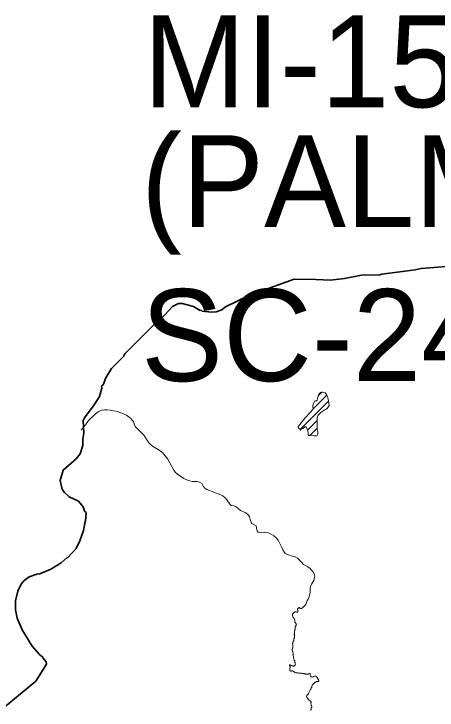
# Model space of a CAD drawing. Extents: x 553962 to 842807, y 8883888 to 9032388.
# Drawn here: x 608939 to 611239, y 8912510 to 8916296 of the extents above; entities that cross this region are included whole.
import ezdxf

# ---------------------------------------------------------------- set-up
doc = ezdxf.new("R2010")
doc.units = 0
doc.header["$LTSCALE"] = 200
doc.linetypes.add('LONG_DASH_SHORT_DASH', pattern=[9.9, 6, -1.2, 1.5, -1.2])
doc.layers.add('6', color=7, linetype='Continuous', lineweight=13)

msp = doc.modelspace()

# ---------------------------------------------------------------- linework, layer by layer
at = {"layer": '6'}
for p, q in [((610565.7, 8914148.7), (610640.2, 8914223.2)), ((610592.8, 8914218.2), (610613.2, 8914238.6)), ((610494, 8914034.6), (610649.5, 8914190.1)), ((610536, 8914034.2), (610587.2, 8914085.3)), ((610547.2, 8914002.9), (610587.8, 8914043.4))]:
    msp.add_line(p, q, dxfattribs=at)
at = {"layer": '6', "linetype": 'LONG_DASH_SHORT_DASH', "lineweight": 35}
for points in [[(609417, 8914259.9), (609414.5, 8914271.5), (609423.4, 8914278), (609438.5, 8914317.1), (609470.2, 8914368), (609534.8, 8914432.1), (609542.7, 8914447.8), (609726.2, 8914632.2), (609735.6, 8914633.7), (609801.8, 8914705.2), (609834.3, 8914720.4), (609853.1, 8914720.4), (609915.1, 8914705.6), (609951.4, 8914683.3), (609956.6, 8914684.2), (609962.2, 8914680.3), (610012.3, 8914673.4), (610039, 8914675), (610068.6, 8914686.7), (610088.4, 8914702.4), (610215.4, 8914764.3), (610462.8, 8914853.2), (610579.4, 8914851.9), (610659.1, 8914847.2), (610736.4, 8914857.9), (610829, 8914875.5), (610927.4, 8914877.4), (610939, 8914881.5), (611120.3, 8914903.8), (611152.1, 8914910.7), (611312, 8914924.8)], [(608880, 8912519.3), (609058.8, 8912666.4), (609116.5, 8912759.3), (609114.9, 8912772.6), (609096.2, 8912793.6), (609097.3, 8912795.6), (609078.6, 8912811.8), (609038.2, 8912857.6), (608983.3, 8912946.8), (608956.3, 8913009.1), (608946.9, 8913054.2), (608947.5, 8913104.1), (608959.7, 8913156.7), (608979, 8913193.9), (608994.6, 8913214.2), (609021.3, 8913233.8), (609062.8, 8913248.6), (609080.9, 8913251), (609139.7, 8913275.3), (609195.1, 8913310.8), (609228, 8913340.4), (609232.6, 8913340.3), (609276.6, 8913389.1), (609297.3, 8913429.6), (609318.1, 8913487), (609324.7, 8913524.3), (609323.1, 8913528.6), (609328.6, 8913536.8), (609332, 8913584.8), (609323.1, 8913590.8), (609315.6, 8913614.7), (609290.5, 8913645.2), (609240.2, 8913670.2), (609212.4, 8913694.1), (609201.8, 8913711), (609190.8, 8913757.9), (609207.3, 8913814.3), (609277.5, 8913876.2), (609298.7, 8913903.7), (609314.4, 8913949), (609314.4, 8913981.9), (609319.5, 8914018.2), (609315.7, 8914084.9), (609322.5, 8914099.7), (609375.2, 8914169.3), (609404.5, 8914214.5), (609417, 8914259.9)]]:
    msp.add_lwpolyline(points, dxfattribs=at)
at = {"layer": '6'}
for points in [[(610550.1, 8914128.2), (610522.6, 8914099.6), (610485.2, 8914054.4), (610484.5, 8914051.4), (610485.8, 8914043.6), (610490.9, 8914038.7), (610495.7, 8914032.3), (610498.2, 8914032.8), (610503.2, 8914038.6), (610511.3, 8914041.6), (610520, 8914049.9), (610522.6, 8914050.8), (610526.2, 8914050.7), (610528.6, 8914048), (610536.9, 8914032.6), (610538.2, 8914010.4), (610539.8, 8914005.3), (610541.1, 8914003.4), (610572.1, 8914000.6), (610584.6, 8914001.8), (610587.4, 8914003), (610591.6, 8914010.9), (610591.8, 8914024.6), (610588.8, 8914032.4), (610588, 8914036.4), (610586.7, 8914070.3), (610587.8, 8914099.9), (610590.6, 8914109.6), (610593.7, 8914113.9), (610608, 8914127.7), (610618.3, 8914134.6), (610625.4, 8914140.7), (610632.9, 8914144.4), (610642.7, 8914150.8), (610652.1, 8914166.7), (610649.1, 8914194), (610643.6, 8914215.7), (610640.1, 8914223.4), (610630.2, 8914235.9), (610618.4, 8914238.7)], [(610618.4, 8914238.7), (610613.1, 8914238.6), (610606, 8914236.5), (610596.3, 8914228.7), (610594.6, 8914224.8), (610586.9, 8914195.9), (610580.3, 8914189.7), (610574.4, 8914190.9), (610570.6, 8914185.2), (610568.3, 8914176.6), (610564.4, 8914166.3), (610563.7, 8914158.5), (610565.8, 8914148.4), (610564.8, 8914145.3), (610550.1, 8914128.2)], [(609417.9, 8914140.3), (609432.3, 8914143), (609446.8, 8914143.1), (609462, 8914141.3), (609500.2, 8914133.9), (609525, 8914125.2), (609551.2, 8914114.5), (609565.8, 8914103.2), (609574.5, 8914094.8), (609590.7, 8914075.3), (609593.5, 8914063.3), (609599.2, 8914050.6), (609647.6, 8914002.6), (609664.4, 8913973.8), (609675.8, 8913959.2), (609691.7, 8913944.3), (609718.8, 8913929.2), (609744.3, 8913912.2), (609754.5, 8913902), (609775.4, 8913874.4), (609799.6, 8913831.8), (609808, 8913815.2), (609816.3, 8913803.9), (609827.9, 8913793.1), (609863.5, 8913769.2), (609883, 8913759.4), (609908.5, 8913753.4), (609934, 8913752.3), (609948.3, 8913750), (609960, 8913741.4), (609967.7, 8913728.2), (609976.3, 8913717.3), (609987.7, 8913708.8), (610063.1, 8913680.4), (610075.6, 8913674.7), (610087.9, 8913664), (610096.3, 8913653.3), (610112.7, 8913629.2), (610116, 8913625.7), (610120.4, 8913623.2), (610133.8, 8913620.9), (610145.7, 8913616.5), (610170.2, 8913594.9), (610199.2, 8913582.2), (610214.4, 8913569.6), (610219.3, 8913560.4), (610223.4, 8913545.4), (610230.4, 8913527.1), (610232.1, 8913525.3), (610240.4, 8913521), (610255.3, 8913511.4), (610259.1, 8913488.4), (610261.4, 8913484.1), (610266.4, 8913478.2), (610271.4, 8913476.7), (610286, 8913476.2), (610299.6, 8913477.2), (610314.8, 8913475.2), (610327.5, 8913471.4), (610351.4, 8913457.7), (610364.5, 8913445.8), (610374.8, 8913433.9), (610381.7, 8913423.5), (610381.7, 8913423.5), (610389.1, 8913409.2)], [(609304.8, 8914031.3), (609316.3, 8914047), (609328.2, 8914061), (609345.4, 8914085), (609380.9, 8914119.9), (609391.6, 8914128.4), (609400.3, 8914134.1), (609417.9, 8914140.3)], [(610389.1, 8913409.2), (610395.4, 8913393.2), (610401.3, 8913381.1), (610409.7, 8913367.4), (610414, 8913362.1), (610427.1, 8913356), (610453.7, 8913346.8), (610468.8, 8913342.4), (610480.8, 8913335.7), (610492.2, 8913325.5), (610503.7, 8913311.6), (610513.8, 8913301.2), (610536.1, 8913288.8), (610548.6, 8913279.7), (610553.6, 8913275), (610564.1, 8913262.7), (610572.3, 8913247.7), (610574, 8913236.7), (610573.8, 8913232.5), (610569.3, 8913214.6), (610556.1, 8913194.1), (610551.1, 8913181.3), (610549.8, 8913168.7), (610549.5, 8913152.5), (610547.4, 8913140.6), (610543.5, 8913125.3), (610537.7, 8913112.6), (610533.2, 8913105.3), (610525.4, 8913084.2)], [(610525.4, 8913084.2), (610525.2, 8913084), (610523.8, 8913081.7), (610522, 8913079.7), (610520.1, 8913078.1), (610517.9, 8913076.8), (610516.1, 8913074.9), (610514.3, 8913072.9), (610512.9, 8913070.6), (610511.1, 8913068.7), (610509, 8913066.9), (610506.9, 8913065.2), (610504.8, 8913063.8), (610502.6, 8913062.7), (610500.1, 8913062.3), (610497.2, 8913062.1), (610495, 8913062.6), (610492.6, 8913063.5), (610491.2, 8913065.9), (610489, 8913067.2), (610486.6, 8913066.3), (610484.7, 8913064.7), (610482.8, 8913062.8), (610481.3, 8913060.5), (610480.3, 8913058.2), (610480.7, 8913055.6), (610481.7, 8913053.3), (610482.2, 8913050.7), (610482.8, 8913048.2), (610482.2, 8913045.7), (610480.8, 8913043.5), (610478.9, 8913041.8), (610476.4, 8913042.4), (610474.2, 8913043.6), (610471.6, 8913044), (610469.1, 8913044.3), (610466.4, 8913044), (610464.5, 8913042.3), (610462.4, 8913040.8), (610460.3, 8913039.3), (610458.4, 8913037.4), (610456.6, 8913035.5), (610455.2, 8913033.2), (610454.1, 8913030.7), (610453.4, 8913027.8), (610453.2, 8913024.5), (610454.2, 8913022), (610454.9, 8913019.4), (610455.8, 8913017), (610457, 8913014.7), (610458.5, 8913012.5), (610460.3, 8913009.9), (610461.9, 8913007.7), (610463.3, 8913005.6), (610464.7, 8913003.4), (610465.7, 8913001.1), (610466.5, 8912998.6), (610466.2, 8912995.8), (610466, 8912993.3), (610466, 8912990.6), (610466.7, 8912988.2), (610468.1, 8912985.8), (610469.7, 8912983.7), (610471.1, 8912981.4), (610472.7, 8912979.4)], [(610472.7, 8912979.4), (610474.1, 8912977.1), (610474.3, 8912974.6), (610473.3, 8912971.7), (610472.1, 8912969.3), (610470.7, 8912966.8), (610469.7, 8912964.4), (610468.6, 8912962), (610468.2, 8912959.3), (610468.7, 8912956.7), (610468.7, 8912954.1), (610468.7, 8912951.1), (610468.2, 8912948.2), (610466.8, 8912945.8), (610465.7, 8912943.4), (610464.4, 8912941.1), (610463.9, 8912938.6), (610463.8, 8912936), (610463.7, 8912933.4), (610464, 8912930.7), (610465.1, 8912928.2), (610465.2, 8912925.7), (610463.9, 8912923.4), (610462.9, 8912921.1), (610462.7, 8912918.6), (610464.4, 8912916.8), (610465.1, 8912914.2), (610465.1, 8912911.5), (610465, 8912908.8), (610464.4, 8912906.3), (610463.5, 8912903.5), (610461.8, 8912901.5), (610460.4, 8912899.3), (610460.5, 8912896.7), (610460.9, 8912894.1), (610461.2, 8912891.5), (610461.1, 8912889)], [(610461.1, 8912889), (610460.2, 8912886.6), (610459, 8912884.1), (610457.3, 8912881.8), (610456.1, 8912879.3), (610455.2, 8912876.8), (610454.5, 8912874.4), (610454.1, 8912871.8), (610453.8, 8912869.2), (610454.6, 8912866.6), (610455.5, 8912864), (610455.9, 8912861.6), (610456.1, 8912859), (610455.8, 8912856.5), (610455.5, 8912853.8), (610455.1, 8912851.4), (610454.6, 8912848.8), (610453.9, 8912846.3), (610453.4, 8912843.8), (610452.7, 8912841.3), (610451.9, 8912838.9), (610451.8, 8912836.3), (610451.7, 8912833.7), (610452, 8912831.1), (610453.3, 8912828.9), (610454.9, 8912826.9), (610456.1, 8912824.6), (610456.9, 8912821.9), (610457.3, 8912819.3), (610457.4, 8912816.7), (610456.8, 8912814.2), (610455.9, 8912811.8), (610456.5, 8912809.3), (610457, 8912806.7), (610457.5, 8912804.1), (610458.1, 8912801.3), (610458.6, 8912798.8), (610459, 8912796.3), (610459.4, 8912793.5), (610459.9, 8912791.1), (610460.2, 8912788.5), (610460.6, 8912785.9), (610461.6, 8912783.6), (610462.8, 8912781.4), (610464.2, 8912779.2), (610465.8, 8912777.2), (610466.5, 8912774.8), (610466.8, 8912772.2), (610467, 8912769.3), (610467.2, 8912766.7), (610467.5, 8912764), (610467.6, 8912761.4), (610467.6, 8912758.8), (610467.5, 8912756.3), (610467.1, 8912753.9), (610465.3, 8912752), (610462.9, 8912750.2), (610460.6, 8912749.4), (610457.8, 8912749.3), (610455.3, 8912749.6), (610453, 8912750.6), (610450.4, 8912750.4), (610447.8, 8912751.3), (610445.6, 8912752.5), (610443.4, 8912753.9)], [(610443.4, 8912753.9), (610441.1, 8912755), (610438.7, 8912755.7), (610436.6, 8912754.2), (610436.6, 8912751.7), (610438.3, 8912749.8), (610440, 8912747.9), (610440.5, 8912745.4), (610440.4, 8912742.7), (610440.2, 8912740), (610439.6, 8912737.5), (610438.9, 8912734.9), (610438.6, 8912732.3), (610438.6, 8912729.7), (610438.8, 8912727.2), (610439.8, 8912724.8), (610441.4, 8912722.4), (610443.5, 8912721), (610446.1, 8912721.6), (610448.4, 8912722.8), (610451.3, 8912723.1), (610453.8, 8912722.7), (610456.3, 8912721.6), (610458.5, 8912720.2), (610460.6, 8912718.7), (610462.7, 8912717), (610464.8, 8912715.6), (610466.8, 8912713.9), (610469.1, 8912712.5), (610471.6, 8912711.9), (610474.2, 8912711.9), (610476.9, 8912711.8), (610479.6, 8912711.8), (610482.2, 8912712.1), (610484.9, 8912711.5), (610487.4, 8912711), (610489.9, 8912710.8)], [(610489.9, 8912710.8), (610492.5, 8912710.9), (610495.2, 8912711.1), (610497.8, 8912711.1), (610500.5, 8912710.7), (610502.8, 8912709.7), (610505.4, 8912709.1), (610508.1, 8912708.8), (610510.9, 8912708.7), (610513.6, 8912708.4), (610516.3, 8912707.8), (610518.8, 8912707.1), (610521.4, 8912706.4), (610523.9, 8912705.7), (610526.8, 8912705.4), (610529.8, 8912705.3), (610532.6, 8912705.2), (610535.2, 8912705.2), (610537.9, 8912705.4), (610540.4, 8912706.1), (610543.1, 8912707.2), (610545.6, 8912707.8), (610548.1, 8912707.8), (610550.1, 8912706.2), (610549.6, 8912703.7), (610548.7, 8912701.3), (610549.3, 8912698.8), (610550.4, 8912696.3), (610551.8, 8912694), (610553.3, 8912691.8), (610555.4, 8912690.4), (610558, 8912689.6), (610560.6, 8912689.5), (610563.1, 8912690), (610565.4, 8912691.3), (610567.7, 8912692.3), (610570.3, 8912693.2), (610572.8, 8912693.9), (610575.6, 8912694.6), (610578.2, 8912694.7), (610580.7, 8912694.3), (610583, 8912692.9), (610584.6, 8912691), (610586, 8912688.9), (610587.2, 8912686.6), (610588.6, 8912684.5), (610589.9, 8912682.3), (610591.3, 8912680.1), (610593, 8912678.1), (610594.4, 8912675.4), (610596.4, 8912670.8)], [(610596.4, 8912670.8), (610596.7, 8912669.8), (610596.7, 8912669.2), (610596.2, 8912667.9), (610595.2, 8912666.8), (610593.2, 8912665.4), (610590.7, 8912664.7), (610588, 8912664.5), (610585.4, 8912664.6), (610583.1, 8912663.3), (610580.5, 8912662.8), (610578.3, 8912661.4), (610576.1, 8912660.1), (610573.9, 8912658.5), (610571.9, 8912656.7), (610570, 8912654.9), (610568.2, 8912652.8), (610566.5, 8912650.8), (610564.6, 8912648.9), (610562.6, 8912647.3), (610560.9, 8912645.4), (610560.2, 8912642.6), (610559.3, 8912640.2), (610558.6, 8912637.8), (610558.2, 8912635.1), (610557.1, 8912632.7), (610555.7, 8912630.5), (610554.6, 8912628), (610552.4, 8912623.1)], [(610552.4, 8912623.1), (610551.4, 8912620.9), (610547.8, 8912614.2), (610544.7, 8912607.2), (610541.2, 8912600.6), (610536.7, 8912594.4), (610532, 8912588.5), (610530, 8912581.1), (610534.2, 8912574.9), (610538.4, 8912568.3), (610544.2, 8912563.2), (610547.2, 8912561.2), (610549.8, 8912559.8), (610551.9, 8912558.4), (610554, 8912555.9), (610554.6, 8912553.2), (610554.3, 8912550.7), (610553.1, 8912548.5), (610552.2, 8912546.2), (610552.2, 8912543.7), (610552.8, 8912541.2), (610554, 8912538.7), (610555.1, 8912536.3), (610556.5, 8912534), (610558, 8912531.5), (610559, 8912529.1), (610559.4, 8912526.5), (610558.6, 8912524.2), (610556.5, 8912522.9), (610554.7, 8912521.2), (610554.1, 8912518.8), (610554.1, 8912516.3), (610554, 8912513.7), (610553.7, 8912510.7), (610553.5, 8912508.2)]]:
    msp.add_lwpolyline(points, dxfattribs=at)

# ---------------------------------------------------------------- texts
for s, p in [('MI-1523', (609642.6, 8915788.7)), ('(PALMEIRA DOS ÍNDIOS)', (609630, 8915136.3)), ('SC-24-X-D-II', (609630, 8914299.2))]:
    msp.add_text(s, height=500, dxfattribs=at).set_placement(p)

doc.saveas('drawing.dxf')
